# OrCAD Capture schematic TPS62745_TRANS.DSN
size C; title: TPS62745: Dual-cell Ultra Low IQ Step Down Converter; rev: 1.0; note: Datasheet: SLVSC68     EVM Guide:
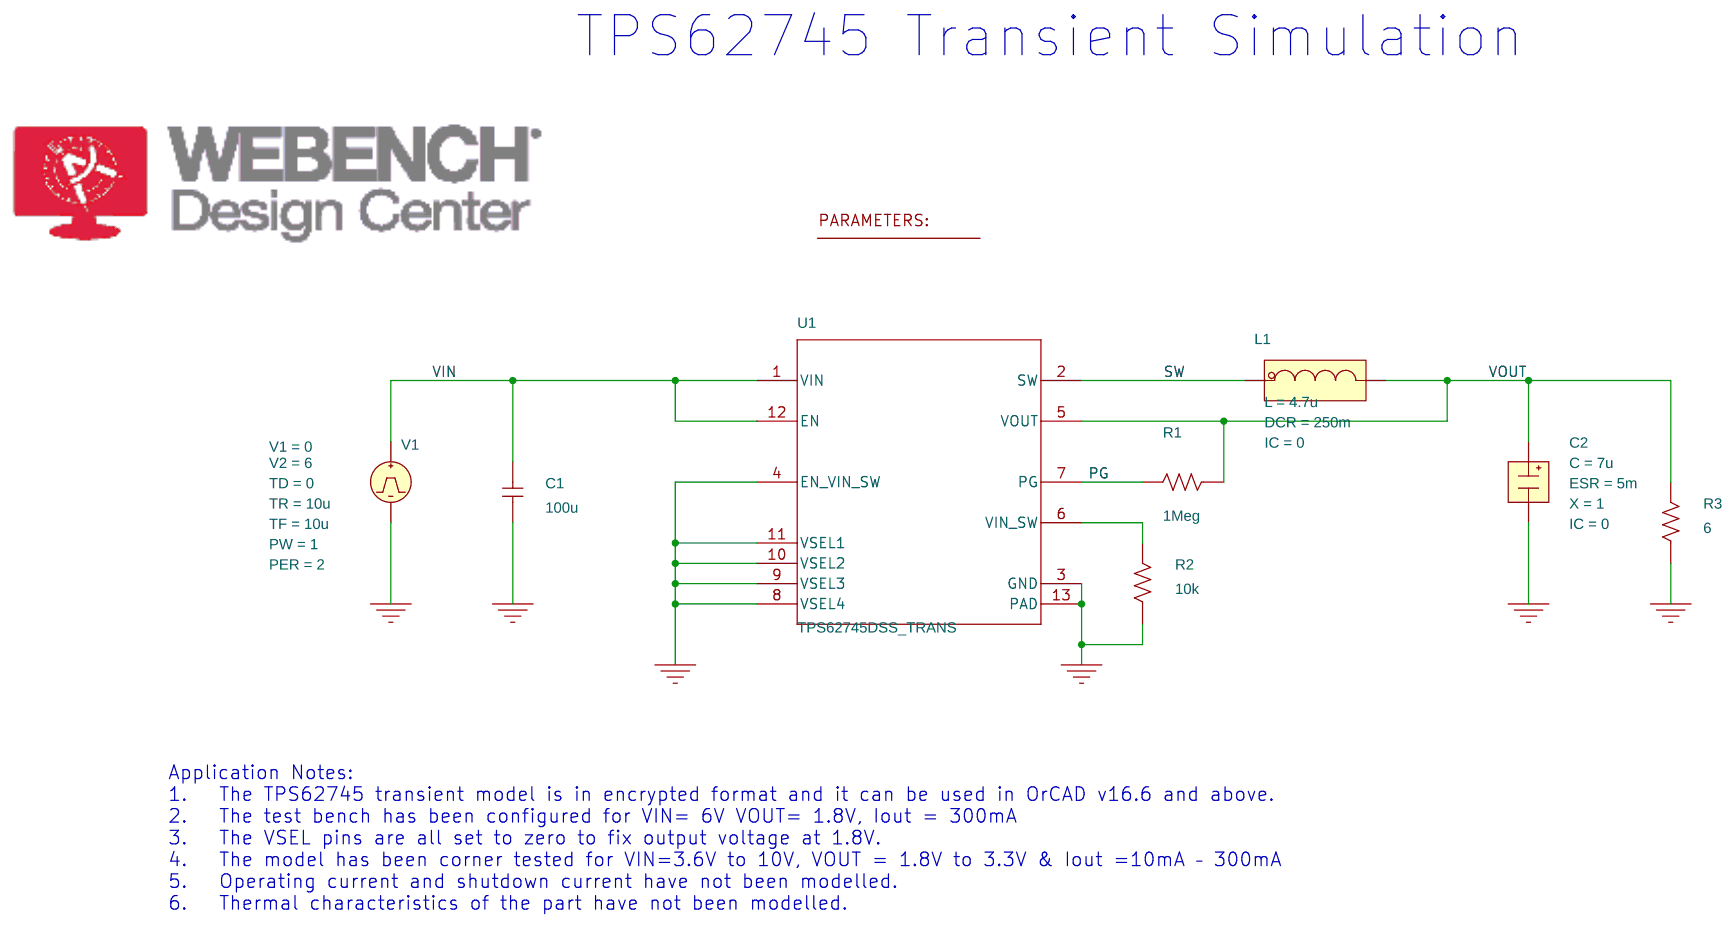
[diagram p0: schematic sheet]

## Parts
1  PARAM
C1  100u  [RAD/CK05]
C2  CESR
L1  LDCR
R1  1Meg  [AX/RC05]
R2  10k  [AX/RC05]
R3  6  [AX/RC05]
U1  TPS62745DSS_TRANS  [DSS0012A]
V1  VPULSE

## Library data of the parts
1 = PARAM: VOUT: 0
C1 = C
C2 = CESR: C: 7u; ESR: 5m; IC: 0; PSpiceTemplate: X^@REFDES %IN %OUT @MODEL PARAMS:  ?C|C=@C||C=100u|  ?ESR|ESR=@ESR||ESR=0.01| ?X|X=@X||X=2|  ?IC|IC=@IC||IC=2|; X: 1
L1 = LDCR: DCR: 250m; IC: 0; L: 4.7u; PSpiceTemplate: X^@REFDES %IN %OUT @MODEL PARAMS:  ?L|L=@L||L=1u|  ?DCR|DCR=@DCR||DCR=0.01| ?IC|IC=@IC||IC=0|
R1-R3 = R
U1 = TPS62745DSS_TRANS
V1 = VPULSE: PER: 2; PW: 1; TD: 0; TF: 10u; TR: 10u; V1: 0; V2: 6

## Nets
VIN: C1.2 U1.1(VIN) U1.12(EN) V1.1(+)
0: C1.1 C2.3(OUT) R2.1 R3.1 U1.3(GND) U1.4(EN_VIN_SW) U1.8(VSEL4) U1.9(VSEL3) U1.10(VSEL2) U1.11(VSEL1) U1.13(PAD) V1.2(-)
PG: R1.2 U1.7(PG)
SW: L1.1(IN) U1.2(SW)
VOUT: C2.1(IN) L1.3(OUT) R1.1 R3.2 U1.5(VOUT)
N14420094: R2.2 U1.6(VIN_SW)

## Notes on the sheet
- TPS62745 Transient Simulation
- Application Notes:
  1.	The TPS62745 transient model is in encrypted format and it can be used in OrCAD v16.6 and above.
  2.	The test bench has been configured for VIN= 6V VOUT= 1.8V, Iout = 300mA
  3.	The VSEL pins are all set to zero to fix output voltage at 1.8V.
  4.	The model has been corner tested for VIN=3.6V to 10V, VOUT = 1.8V to 3.3V & Iout =10mA – 300mA
  5.	Operating current and shutdown current have not been modelled.
  6.	Thermal characteristics of the part have not been modelled.
